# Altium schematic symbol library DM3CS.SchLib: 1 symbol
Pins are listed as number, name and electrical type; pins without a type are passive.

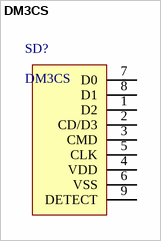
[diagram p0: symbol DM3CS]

## DM3CS
designator SD?
DM3CS Micro SD Card Holder
footprint DM3CS (DM3CS Micro SD Card Holder)
pins: 1 D2, 2 CD/D3, 3 CMD, 4 VDD, 5 CLK, 6 VSS, 7 D0, 8 D1, 9 DETECT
